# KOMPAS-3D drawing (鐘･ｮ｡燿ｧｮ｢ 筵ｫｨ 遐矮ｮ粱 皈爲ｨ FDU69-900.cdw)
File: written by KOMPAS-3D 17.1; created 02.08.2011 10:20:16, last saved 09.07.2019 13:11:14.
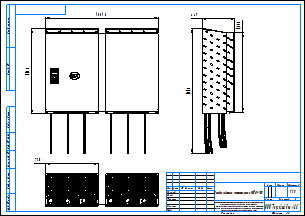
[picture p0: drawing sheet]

Title block, sheet 1: name: Преобразователи частоты серии FDU69-900; scale: 1:10; sheets: 1; sheet format: A3; stored path: \\adlc.lan\data\АДЛ_ПКД\3D-модели\Поставщики\Оборудование Emotron\Преобразователи частоты\Серия FDU 2.0\KOMPAS 2D\Преобразователи частоты серии FDU69-900.cdw

Views: Спереди 1
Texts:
  Рама для чертежей
  Лит-Масса-Масштаб
  Материал-Предприятие
  Масштаб
  Изм.
  Лист
  № докум.
  Подп.
  Дата
  Лит.
  Разраб.
  Пров.
  Т.контр.
  Листов
  Внимание! Данный продукт является объектом авторского права ООО «Торговый Дом АДЛ».
  Запрещается изменение, копирование, распространение
  (в том числе путем копирования на другие сайты и ресурсы в Интернете)
  или любое иное использование информации и объектов без предварительного
  согласия правообладателя (ООО «Торговый Дом АДЛ»).
  Н.контр.
  Утв.
  ООО "Торговый дом АДЛ"
  Изменение
  Номер документа
  Подпись
  Обозначение документа
  Наименование изделия
  Масса изделия по ГОСТ 2.109-73
  Порядковый номер листа
  Общее количество листов в документе
  Характер работы, выполненной лицом, подписавшим документ
  Наименование или индекс предприятия, выпускающего документ
  Инв. № подл.
  Подп. и дата
  Взам. инв. №
  Инв. № дубл.
  Инвентарный номер подлинника по ГОСТ 2.501-68
  Подпись принявшего подлинник в отдел технической документации
  Инвентарный номер подлинника, взамен которого выпущен данный подлинник
  Инвентарный номер дубликата по ГОСТ 2.502-68
  Подпись принявшего дубликат в отдел технической документации
  Справ. №
  Перв. примен.
  Обозначение документа, взамен или на основании которого выпущен данный документ
  Обозначение документа, в котором впервые записан данный документ
  Подпись лица, копировавшего чертеж
  Обозначение формата листа
  !Рама для чертежа
Dimensions and other numbers on the sheet: 1561,5; 1176; 730; 1718; 1096; 449; 1:10; 1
